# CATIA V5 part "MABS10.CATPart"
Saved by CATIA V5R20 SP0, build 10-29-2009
Part number: MABS10
Definition: NONE
Nomenclature: MABS10
Source: Unknown
Description: MABS10
Bounding box of the stored display mesh (mm): x 0 to 12, y -5 to 5, z -5 to 5
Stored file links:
  C:\Users\Utente\Desktop\IO LAVORO\3D X SITO CF\X SITO\PLASTICA\CFMR\MABS10.CATPart
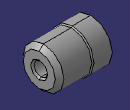
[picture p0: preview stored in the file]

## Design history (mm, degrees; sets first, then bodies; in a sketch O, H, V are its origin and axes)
Body1 "MABS10" (main body)
  Solid1: solid without history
